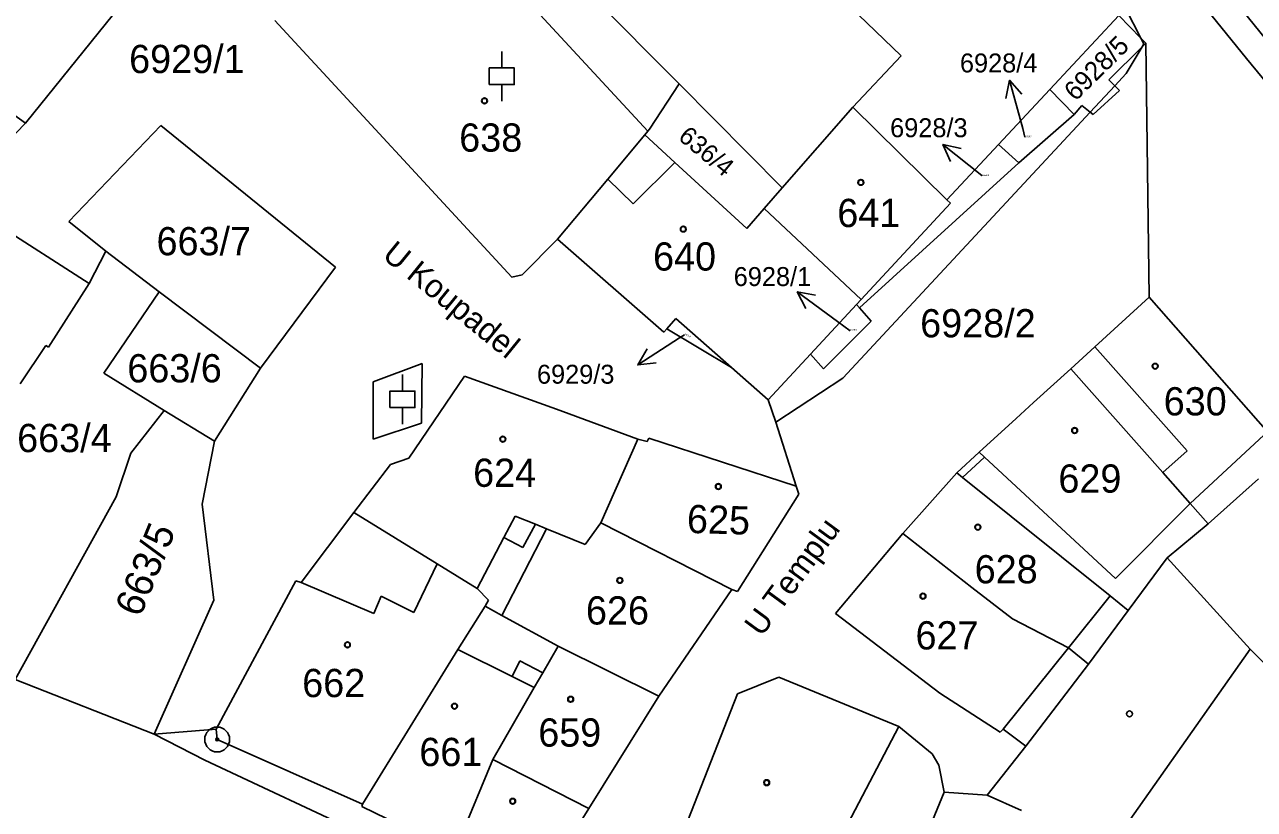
# Model space of a CAD drawing. Extents: x -593183 to -588034, y -1130415 to -1124994.
# Drawn here: x -591094.9 to -591020.9, y -1128867.8 to -1128820.6 of the extents above; entities that cross this region are included whole.
import ezdxf

# ---------------------------------------------------------------- set-up
doc = ezdxf.new("R2010")
doc.units = 0
for name, color, linetype in [('Vrstva 1', 7, 'Continuous'), ('Vrstva 15', 7, 'Continuous'), ('Vrstva 16', 7, 'Continuous'), ('Vrstva 18', 7, 'Continuous'), ('Vrstva 19', 7, 'Continuous'), ('Vrstva 24', 7, 'Continuous'), ('Vrstva 25', 7, 'Continuous'), ('Vrstva 4', 7, 'Continuous')]:
    doc.layers.add(name, color=color, linetype=linetype)

msp = doc.modelspace()

# ---------------------------------------------------------------- linework, layer by layer
at = {"layer": 'Vrstva 1'}
for p, q in [((-591070.26, -1128809.27), (-591055.5, -1128824.15)), ((-591084.83, -1128814.07), (-591094.84, -1128826.52)), ((-591044.71, -1128820), (-591042.14, -1128822.46)), ((-591029.03, -1128820.03), (-591033.18, -1128824.48)), ((-591029.03, -1128820.03), (-591027.7, -1128821.39)), ((-591102.73, -1128820.83), (-591094.84, -1128826.52)), ((-591079.83, -1128820.33), (-591065.57, -1128835.78)), ((-591027.7, -1128821.39), (-591027.41, -1128821.69)), ((-591027.62, -1128821.91), (-591029.64, -1128823.9)), ((-591027.41, -1128821.69), (-591027.62, -1128821.91)), ((-591027.41, -1128821.69), (-591027.21, -1128837)), ((-591042.14, -1128822.46), (-591045.05, -1128825.56)), ((-591055.5, -1128824.15), (-591057.28, -1128826.88)), ((-591055.5, -1128824.15), (-591049.29, -1128830.41)), ((-591033.18, -1128824.48), (-591036.27, -1128827.8)), ((-591033.18, -1128824.48), (-591031.71, -1128826)), ((-591029, -1128824.54), (-591030.58, -1128825.99)), ((-591029.64, -1128823.9), (-591029.27, -1128824.27)), ((-591029.27, -1128824.27), (-591029, -1128824.54)), ((-591045.05, -1128825.56), (-591049.29, -1128830.41)), ((-591045.05, -1128825.56), (-591039.39, -1128831.14)), ((-591031.71, -1128826), (-591035.06, -1128828.9)), ((-591031.25, -1128825.45), (-591031.71, -1128826)), ((-591031.25, -1128825.45), (-591030.75, -1128825.85)), ((-591030.75, -1128825.85), (-591030.58, -1128825.99)), ((-591094.84, -1128826.52), (-591099.18, -1128830.94)), ((-591086.71, -1128826.66), (-591092.23, -1128832.44)), ((-591086.71, -1128826.66), (-591076.19, -1128835.18)), ((-591057.57, -1128827.21), (-591059.8, -1128829.89)), ((-591057.39, -1128827), (-591057.57, -1128827.21)), ((-591057.57, -1128827.21), (-591055.75, -1128828.88)), ((-591057.28, -1128826.88), (-591057.39, -1128827)), ((-591036.27, -1128827.8), (-591039.39, -1128831.14)), ((-591036.27, -1128827.8), (-591035.06, -1128828.9)), ((-591055.75, -1128828.88), (-591051.43, -1128832.86)), ((-591035.06, -1128828.9), (-591044.65, -1128837.63)), ((-591059.8, -1128829.89), (-591062.82, -1128833.49)), ((-591049.29, -1128830.41), (-591050.38, -1128831.65)), ((-591099.18, -1128830.94), (-591091.02, -1128836.16)), ((-591039.39, -1128831.14), (-591039.17, -1128831.34)), ((-591050.38, -1128831.65), (-591051.43, -1128832.86)), ((-591050.38, -1128831.65), (-591044.54, -1128837.13)), ((-591039.17, -1128831.34), (-591044.54, -1128837.13)), ((-591092.23, -1128832.44), (-591090.02, -1128834.23)), ((-591062.82, -1128833.49), (-591064.94, -1128835.64)), ((-591062.82, -1128833.49), (-591056.43, -1128839.1)), ((-591090.02, -1128834.23), (-591091.02, -1128836.16)), ((-591090.02, -1128834.23), (-591086.81, -1128836.66)), ((-591076.19, -1128835.18), (-591080.71, -1128841.27)), ((-591064.94, -1128835.64), (-591065.57, -1128835.78)), ((-591091.02, -1128836.16), (-591093.46, -1128840.01)), ((-591086.81, -1128836.66), (-591090.14, -1128841.57)), ((-591086.81, -1128836.66), (-591080.71, -1128841.27)), ((-591044.54, -1128837.13), (-591044.82, -1128837.43)), ((-591027.21, -1128837), (-591030.48, -1128839.98)), ((-591027.21, -1128837), (-591020.06, -1128845.11)), ((-591044.82, -1128837.43), (-591047.6, -1128840.43)), ((-591044.82, -1128837.43), (-591044.65, -1128837.63)), ((-591044.65, -1128837.63), (-591043.94, -1128838.44)), ((-591055.7, -1128838.27), (-591056.24, -1128838.89)), ((-591055.7, -1128838.27), (-591052.34, -1128841.23)), ((-591043.94, -1128838.44), (-591046.81, -1128841.31)), ((-591056.24, -1128838.89), (-591056.43, -1128839.1)), ((-591056.24, -1128838.89), (-591052.34, -1128841.23)), ((-591093.63, -1128839.91), (-591095.16, -1128842.2)), ((-591093.63, -1128839.91), (-591093.46, -1128840.01)), ((-591030.48, -1128839.98), (-591031.93, -1128841.3)), ((-591047.6, -1128840.43), (-591050.14, -1128843.17)), ((-591047.6, -1128840.43), (-591046.81, -1128841.31)), ((-591090.14, -1128841.57), (-591086.51, -1128843.81)), ((-591080.71, -1128841.27), (-591083.48, -1128845.66)), ((-591052.34, -1128841.23), (-591050.14, -1128843.17)), ((-591031.93, -1128841.3), (-591034.17, -1128843.34)), ((-591031.93, -1128841.3), (-591026.39, -1128847.55)), ((-591068.42, -1128841.75), (-591071.77, -1128846.68)), ((-591068.42, -1128841.75), (-591062.88, -1128843.74)), ((-591086.51, -1128843.81), (-591088.5, -1128846.38)), ((-591086.51, -1128843.81), (-591083.48, -1128845.66)), ((-591062.88, -1128843.74), (-591057.98, -1128845.53)), ((-591050.14, -1128843.17), (-591049.67, -1128844.52)), ((-591034.17, -1128843.34), (-591035.22, -1128844.3)), ((-591049.67, -1128844.52), (-591048.46, -1128848.36)), ((-591035.22, -1128844.3), (-591037.44, -1128846.33)), ((-591083.48, -1128845.66), (-591084.22, -1128849.46)), ((-591057.98, -1128845.53), (-591060.22, -1128850.58)), ((-591057.98, -1128845.53), (-591057.43, -1128845.69)), ((-591057.32, -1128845.48), (-591057.43, -1128845.69)), ((-591057.32, -1128845.48), (-591048.46, -1128848.36)), ((-591088.5, -1128846.38), (-591089.4, -1128849.02)), ((-591071.77, -1128846.68), (-591072.88, -1128847.07)), ((-591037.44, -1128846.33), (-591038.79, -1128847.56)), ((-591072.88, -1128847.07), (-591075.08, -1128849.95)), ((-591026.39, -1128847.55), (-591024.73, -1128849.42)), ((-591038.79, -1128847.56), (-591042.03, -1128851.22)), ((-591038.79, -1128847.56), (-591038.44, -1128847.84)), ((-591038.44, -1128847.84), (-591029.56, -1128854.98)), ((-591020.62, -1128847.92), (-591023.65, -1128850.64)), ((-591089.4, -1128849.02), (-591095.47, -1128860)), ((-591048.29, -1128848.85), (-591051.99, -1128854.72)), ((-591048.46, -1128848.36), (-591048.29, -1128848.85)), ((-591084.22, -1128849.46), (-591083.51, -1128855.24)), ((-591024.73, -1128849.42), (-591023.65, -1128850.64)), ((-591075.08, -1128849.95), (-591078.26, -1128854.17)), ((-591075.08, -1128849.95), (-591070.07, -1128853.05)), ((-591065.38, -1128850.17), (-591066.05, -1128851.46)), ((-591065.38, -1128850.17), (-591064.15, -1128850.66)), ((-591064.15, -1128850.66), (-591063.48, -1128850.94)), ((-591063.48, -1128850.94), (-591061.15, -1128851.88)), ((-591060.22, -1128850.58), (-591061.15, -1128851.88)), ((-591060.22, -1128850.58), (-591052.32, -1128854.59)), ((-591042.03, -1128851.22), (-591046.08, -1128856.04)), ((-591042.03, -1128851.22), (-591037.88, -1128854.46)), ((-591023.65, -1128850.64), (-591026.12, -1128852.68)), ((-591066.05, -1128851.46), (-591067.65, -1128854.54)), ((-591026.12, -1128852.68), (-591028.47, -1128855.86)), ((-591070.07, -1128853.05), (-591067.65, -1128854.54)), ((-591078.57, -1128854.07), (-591083.38, -1128862.99)), ((-591078.57, -1128854.07), (-591078.26, -1128854.17)), ((-591067.65, -1128854.54), (-591066.98, -1128855.23)), ((-591052.32, -1128854.59), (-591056.73, -1128861.01)), ((-591052.32, -1128854.59), (-591051.99, -1128854.72)), ((-591037.88, -1128854.46), (-591035.44, -1128856.36)), ((-591083.51, -1128855.24), (-591087.11, -1128863.3)), ((-591067.18, -1128855.6), (-591068.82, -1128858.21)), ((-591066.98, -1128855.23), (-591067.18, -1128855.6)), ((-591067.18, -1128855.6), (-591066.17, -1128856.15)), ((-591029.56, -1128854.98), (-591028.47, -1128855.86)), ((-591066.17, -1128856.15), (-591062.79, -1128858)), ((-591046.08, -1128856.04), (-591039.81, -1128860.84)), ((-591035.44, -1128856.36), (-591032.07, -1128858.11)), ((-591028.47, -1128855.86), (-591030.85, -1128859.08)), ((-591068.82, -1128858.21), (-591074.57, -1128867.51)), ((-591062.79, -1128858), (-591063.71, -1128859.61)), ((-591062.79, -1128858), (-591056.73, -1128861.01)), ((-591032.07, -1128858.11), (-591030.85, -1128859.08)), ((-591030.85, -1128859.08), (-591034.62, -1128864.02)), ((-591095.47, -1128860), (-591087.11, -1128863.3)), ((-591063.71, -1128859.61), (-591064.22, -1128860.5)), ((-591049.49, -1128859.87), (-591051.99, -1128860.88)), ((-591049.49, -1128859.87), (-591042.27, -1128862.83)), ((-591064.22, -1128860.5), (-591066.71, -1128864.82)), ((-591051.99, -1128860.88), (-591058.32, -1128876.96)), ((-591039.81, -1128860.84), (-591036.17, -1128863.18)), ((-591056.73, -1128861.01), (-591060.94, -1128867.77)), ((-591083.38, -1128862.99), (-591087.11, -1128863.3)), ((-591083.38, -1128862.99), (-591083.31, -1128863.62)), ((-591042.27, -1128862.83), (-591045.35, -1128868.7)), ((-591042.27, -1128862.83), (-591040.26, -1128864.48)), ((-591035.99, -1128862.99), (-591036.17, -1128863.18)), ((-591035.99, -1128862.99), (-591034.62, -1128864.02)), ((-591083.31, -1128863.62), (-591074.57, -1128867.51)), ((-591040.26, -1128864.48), (-591039.87, -1128865.17)), ((-591034.62, -1128864.02), (-591036.95, -1128866.97)), ((-591066.71, -1128864.82), (-591069.01, -1128870.37)), ((-591066.71, -1128864.82), (-591060.94, -1128867.77)), ((-591039.87, -1128865.17), (-591039.55, -1128866.8)), ((-591039.55, -1128866.8), (-591041.52, -1128871.56)), ((-591039.55, -1128866.8), (-591036.95, -1128866.97)), ((-591074.57, -1128867.51), (-591074.6, -1128867.65)), ((-591036.95, -1128866.97), (-591034.89, -1128867.89)), ((-591074.6, -1128867.65), (-591069.01, -1128870.37)), ((-591060.94, -1128867.77), (-591064.03, -1128872.76))]:
    msp.add_line(p, q, dxfattribs=at)
at = {"layer": 'Vrstva 16'}
for p, q in [((-591034.68, -1128827.36), (-591034.82, -1128826.83)), ((-591037.26, -1128829.69), (-591037.28, -1128829.67)), ((-591045.21, -1128839.01), (-591045.97, -1128838.45)), ((-591055.18, -1128839.25), (-591055.47, -1128839.44))]:
    msp.add_line(p, q, dxfattribs=at)
at = {"layer": 'Vrstva 24'}
for radius in [0.75, 0.0903]:
    msp.add_circle((-591083.31, -1128863.62), radius, dxfattribs=at)
at = {"layer": 'Vrstva 25'}
for p, q in [((-591066.18, -1128823.19), (-591066.18, -1128822.19)), ((-591066.18, -1128824.19), (-591066.18, -1128825.19)), ((-591034.82, -1128826.83), (-591035.607, -1128823.935)), ((-591037.28, -1128829.67), (-591039.625, -1128827.8)), ((-591045.97, -1128838.45), (-591048.39, -1128836.677)), ((-591055.47, -1128839.44), (-591057.992, -1128841.065)), ((-591072.16, -1128842.64), (-591072.16, -1128841.64)), ((-591072.16, -1128843.64), (-591072.16, -1128844.64))]:
    msp.add_line(p, q, dxfattribs=at)
for points in [[(-591066.93, -1128824.19), (-591065.43, -1128824.19), (-591065.43, -1128823.19), (-591066.93, -1128823.19)], [(-591072.91, -1128843.64), (-591071.41, -1128843.64), (-591071.41, -1128842.64), (-591072.91, -1128842.64)]]:
    msp.add_lwpolyline(points, close=True, dxfattribs=at)
for points in [[(-591035.827, -1128825.031), (-591035.607, -1128823.935), (-591034.862, -1128824.769)], [(-591039.155, -1128828.814), (-591039.625, -1128827.8), (-591038.532, -1128828.032)], [(-591047.879, -1128837.671), (-591048.39, -1128836.677), (-591047.288, -1128836.865)], [(-591056.881, -1128840.943), (-591057.992, -1128841.065), (-591057.422, -1128840.103)]]:
    msp.add_lwpolyline(points, dxfattribs=at)
for centre, radius in [((-591067.22, -1128825.17), 0.175), ((-591067.22, -1128825.17), 0.15), ((-591044.56, -1128830.08), 0.175), ((-591044.56, -1128830.08), 0.15), ((-591055.25, -1128832.89), 0.175), ((-591055.25, -1128832.89), 0.15), ((-591026.84, -1128841.15), 0.175), ((-591026.84, -1128841.15), 0.15), ((-591031.69, -1128845.02), 0.175), ((-591031.69, -1128845.02), 0.15), ((-591066.11, -1128845.54), 0.175), ((-591066.11, -1128845.54), 0.15), ((-591053.14, -1128848.39), 0.175), ((-591053.14, -1128848.39), 0.15), ((-591037.52, -1128850.84), 0.175), ((-591037.52, -1128850.84), 0.15), ((-591059.07, -1128854.04), 0.175), ((-591059.07, -1128854.04), 0.15), ((-591040.82, -1128854.99), 0.175), ((-591040.82, -1128854.99), 0.15), ((-591075.47, -1128857.92), 0.175), ((-591075.47, -1128857.92), 0.15), ((-591069.02, -1128861.62), 0.175), ((-591069.02, -1128861.62), 0.15), ((-591062.03, -1128861.2), 0.175), ((-591062.03, -1128861.2), 0.15), ((-591028.39, -1128862.08), 0.175), ((-591050.23, -1128866.22), 0.175), ((-591050.23, -1128866.22), 0.15), ((-591065.52, -1128867.34), 0.175), ((-591065.52, -1128867.34), 0.15)]:
    msp.add_circle(centre, radius, dxfattribs=at)
at = {"layer": 'Vrstva 4'}
for p, q in [((-591036.09, -1128804.38), (-591021.34, -1128822.62)), ((-591071.96, -1128811.21), (-591057.39, -1128827)), ((-591025.95, -1128814.27), (-591019.87, -1128821.86)), ((-591028.61, -1128819.63), (-591027.7, -1128821.39)), ((-591027.7, -1128821.39), (-591027.52, -1128821.74)), ((-591027.62, -1128821.91), (-591028.59, -1128823.53)), ((-591027.52, -1128821.74), (-591027.62, -1128821.91)), ((-591021.34, -1128822.62), (-590986.45, -1128865.14)), ((-591028.59, -1128823.53), (-591029.27, -1128824.27)), ((-591029.27, -1128824.27), (-591030.75, -1128825.85)), ((-591030.75, -1128825.85), (-591045.64, -1128841.87)), ((-591055.75, -1128828.88), (-591058.27, -1128831.38)), ((-591059.8, -1128829.89), (-591058.27, -1128831.38)), ((-591030.48, -1128839.98), (-591024.92, -1128846.25)), ((-591070.96, -1128840.99), (-591073.91, -1128842.09)), ((-591070.96, -1128840.99), (-591071.01, -1128844.58)), ((-591073.91, -1128842.09), (-591073.91, -1128845.54)), ((-591045.64, -1128841.87), (-591049.67, -1128844.52)), ((-591071.01, -1128844.58), (-591073.91, -1128845.54)), ((-591020.31, -1128845.29), (-591024.73, -1128849.42)), ((-591037.12, -1128846.63), (-591038.44, -1128847.84)), ((-591037.44, -1128846.33), (-591037.12, -1128846.63)), ((-591037.12, -1128846.63), (-591029.23, -1128853.93)), ((-591024.92, -1128846.25), (-591026.39, -1128847.55)), ((-591024.73, -1128849.42), (-591029.23, -1128853.93)), ((-591063.48, -1128850.94), (-591066.17, -1128856.15)), ((-591064.15, -1128850.66), (-591064.91, -1128852.06)), ((-591066.05, -1128851.46), (-591064.91, -1128852.06)), ((-591026.12, -1128852.68), (-591021.12, -1128858.18)), ((-591070.07, -1128853.05), (-591071.47, -1128855.97)), ((-591078.26, -1128854.17), (-591073.88, -1128856.03)), ((-591073.44, -1128854.99), (-591073.88, -1128856.03)), ((-591073.44, -1128854.99), (-591071.47, -1128855.97)), ((-591029.56, -1128854.98), (-591032.07, -1128858.11)), ((-591068.82, -1128858.21), (-591065.56, -1128859.83)), ((-591032.07, -1128858.11), (-591035.99, -1128862.99)), ((-591021.12, -1128858.18), (-591029.66, -1128870.29)), ((-591021.12, -1128858.18), (-591014.3, -1128865.15)), ((-591065.09, -1128858.88), (-591065.56, -1128859.83)), ((-591065.09, -1128858.88), (-591063.71, -1128859.61)), ((-591065.56, -1128859.83), (-591064.22, -1128860.5)), ((-591087.11, -1128863.3), (-591084.06, -1128864.87)), ((-591084.06, -1128864.87), (-591064.7, -1128873.91))]:
    msp.add_line(p, q, dxfattribs=at)

# ---------------------------------------------------------------- texts
at = {"layer": 'Vrstva 15'}
for s, rotation, p in [('U Koupadel', 320.87196, (-591073.44, -1128834.59)), ('U Templu', 53.73018, (-591050.54, -1128857.49))]:
    msp.add_text(s, height=1.4, rotation=rotation, dxfattribs=at).set_placement(p)
at = {"layer": 'Vrstva 16'}
for s, p in [('6928/4', (-591038.597, -1128823.46)), ('6928/3', (-591042.8, -1128827.36)), ('6928/1', (-591052.215, -1128836.32)), ('6929/3', (-591064.059, -1128842.2))]:
    msp.add_text(s, height=1.14, dxfattribs=at).set_placement(p)
at = {"layer": 'Vrstva 18'}
for s, height, rotation, p in [('6928/5', 1.14, 44.76807, (-591031.64, -1128825.24)), ('636/4', 1.1, 320.32818, (-591055.62, -1128827.45)), ('6929/3', 0.1, 332.30052, (-591055.18, -1128839.25)), ('663/5', 1.7, 67.76199, (-591087.94, -1128856.32))]:
    msp.add_text(s, height=height, rotation=rotation, dxfattribs=at).set_placement(p)
for s, height, p in [('6929/1', 1.7, (-591088.61, -1128823.5)), ('6928/4', 0.1, (-591034.68, -1128827.36)), ('6928/3', 0.1, (-591037.26, -1128829.69)), ('663/7', 1.7, (-591086.96, -1128834.47)), ('6928/2', 1.7, (-591040.99, -1128839.41)), ('6928/1', 0.1, (-591045.21, -1128839.01)), ('663/6', 1.7, (-591088.72, -1128842.12)), ('663/4', 1.7, (-591095.35, -1128846.32))]:
    msp.add_text(s, height=height, dxfattribs=at).set_placement(p)
at = {"layer": 'Vrstva 19'}
for s, p in [('638', (-591068.74, -1128828.23)), ('641', (-591045.98, -1128832.77)), ('640', (-591057.07, -1128835.39)), ('630', (-591026.33, -1128844.11)), ('624', (-591067.9, -1128848.41)), ('629', (-591032.67, -1128848.76)), ('628', (-591037.71, -1128854.22)), ('626', (-591061.11, -1128856.7)), ('627', (-591041.27, -1128858.2)), ('662', (-591078.19, -1128861.07)), ('659', (-591063.98, -1128864.05)), ('661', (-591071.14, -1128865.22))]:
    msp.add_text(s, height=1.7, dxfattribs=at).set_placement(p)
msp.add_text('625', height=1.7, rotation=358.27362, dxfattribs=at).set_placement((-591055.05, -1128851.18))

doc.saveas('drawing.dxf')
